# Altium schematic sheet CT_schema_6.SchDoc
size 278 x 170 mm
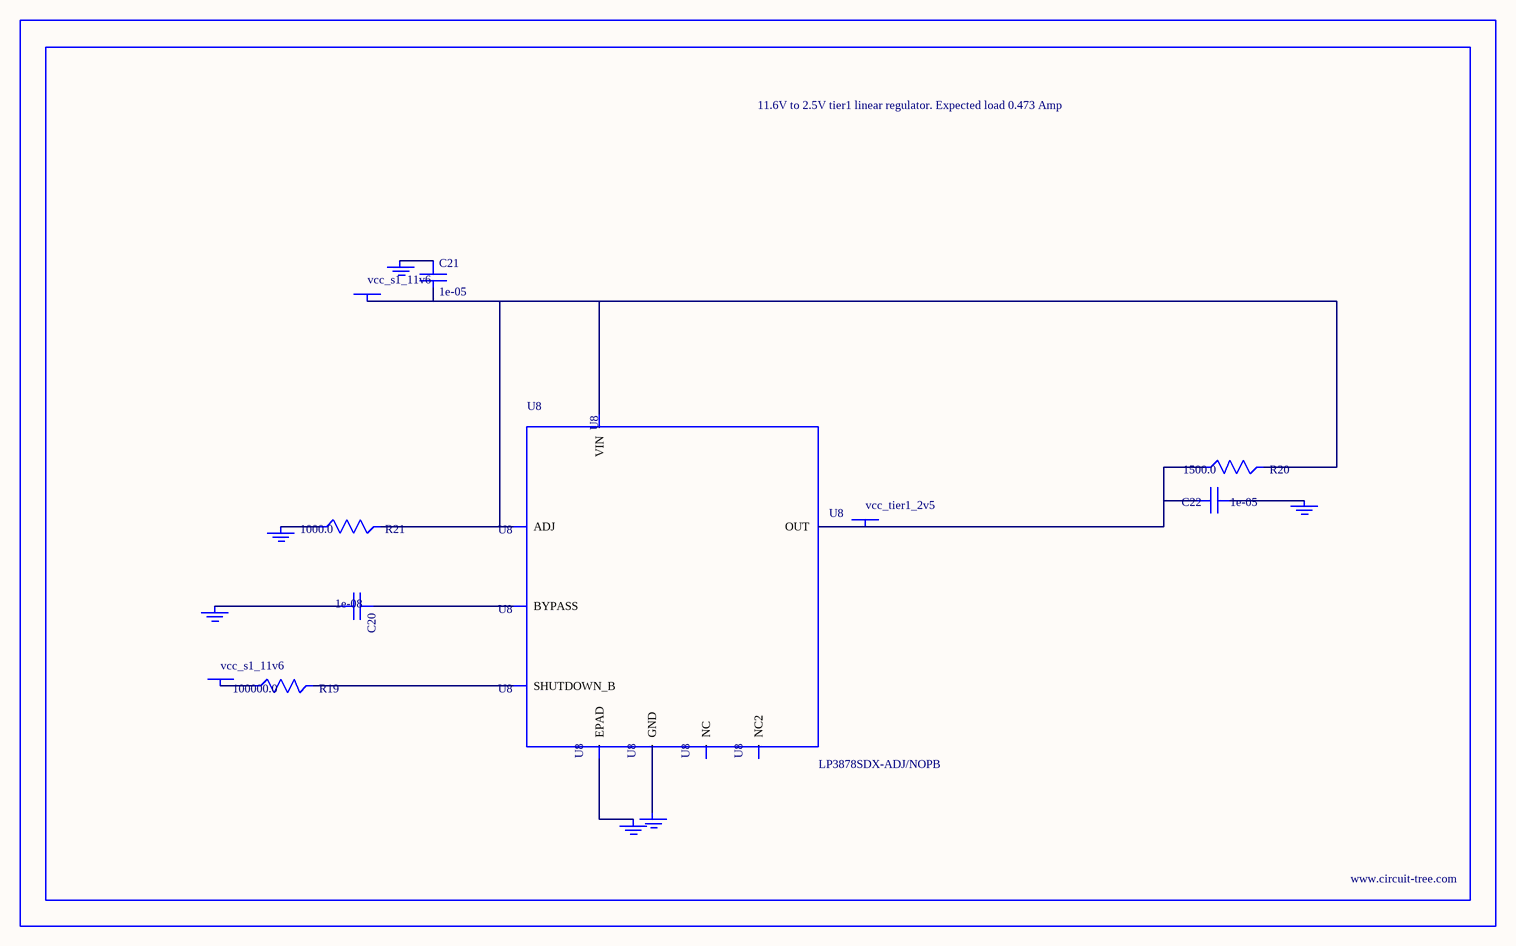
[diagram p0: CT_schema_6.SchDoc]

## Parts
BORDER5  (no value)
C20  1e-08  [C0402]
C21  1e-05  [C1210]
C22  1e-05  [C1210]
GND_INSTANCE_5_0  (no value)
GND_INSTANCE_5_1  (no value)
GND_INSTANCE_5_2  (no value)
GND_INSTANCE_5_3  (no value)
GND_INSTANCE_5_4  (no value)
GND_INSTANCE_5_5  (no value)
POWER_INSTANCE_5_0  vcc_s1_11v6
POWER_INSTANCE_5_1  vcc_s1_11v6
POWER_INSTANCE_5_2  vcc_tier1_2v5
R19  100000.0  [R0603]
R20  1500.0  [R0603]
R21  1000.0  [R0603]
U8  LP3878SDX-ADJ/NOPB  [WSON-8]

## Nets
NetC20_1: C20.1 U8.1(BYPASS)
NetC20_2: C20.2 GND_INSTANCE_5_0.0(GND)
NetC21_1: C21.1 GND_INSTANCE_5_1.0(GND)
NetC21_2: C21.2 POWER_INSTANCE_5_0.0(PWR) R20.2 R21.2 U8.4(VIN) U8.6(ADJ)
NetC22_1: C22.1 GND_INSTANCE_5_2.0(GND)
NetC22_2: C22.2 POWER_INSTANCE_5_2.0(PWR) R20.1 U8.5(OUT)
NetGND_INSTANCE_5_3_0: GND_INSTANCE_5_3.0(GND) R21.1
NetGND_INSTANCE_5_4_0: GND_INSTANCE_5_4.0(GND) U8.PAD(EPAD)
NetGND_INSTANCE_5_5_0: GND_INSTANCE_5_5.0(GND) U8.3(GND)
NetPOWER_INSTANCE_5_1_0: POWER_INSTANCE_5_1.0(PWR) R19.1
NetR19_2: R19.2 U8.8(SHUTDOWN_B)

Not connected (* = marked no-connect by the designer): U8 2(NC) 7(NC2)

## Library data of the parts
BORDER5 = BORDER_PAGE5
C20 = C0402C103K3RAC
C21 = C1210C106K5PACTU
C22 = GRM32DR61E106MA12L
GND_INSTANCE_5_0-GND_INSTANCE_5_5 = GND
POWER_INSTANCE_5_0-POWER_INSTANCE_5_2 = PWR
R19 = RC0603JR-07100KL
R20 = RC0603JR-071K5L
R21 = RC0603JR-071KL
